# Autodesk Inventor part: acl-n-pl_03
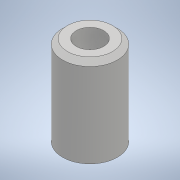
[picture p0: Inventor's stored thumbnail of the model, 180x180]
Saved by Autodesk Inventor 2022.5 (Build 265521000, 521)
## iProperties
Part Number: acl-n-pl_03
Material: 一般
Document SubType Name: Modeling
Designer: ImaoCorp
Density: 1 g/cm^3
Appearance: 既定
Author: ImaoCorp
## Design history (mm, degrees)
feature "acl-n-pl_03"
node "ソリッド1"
